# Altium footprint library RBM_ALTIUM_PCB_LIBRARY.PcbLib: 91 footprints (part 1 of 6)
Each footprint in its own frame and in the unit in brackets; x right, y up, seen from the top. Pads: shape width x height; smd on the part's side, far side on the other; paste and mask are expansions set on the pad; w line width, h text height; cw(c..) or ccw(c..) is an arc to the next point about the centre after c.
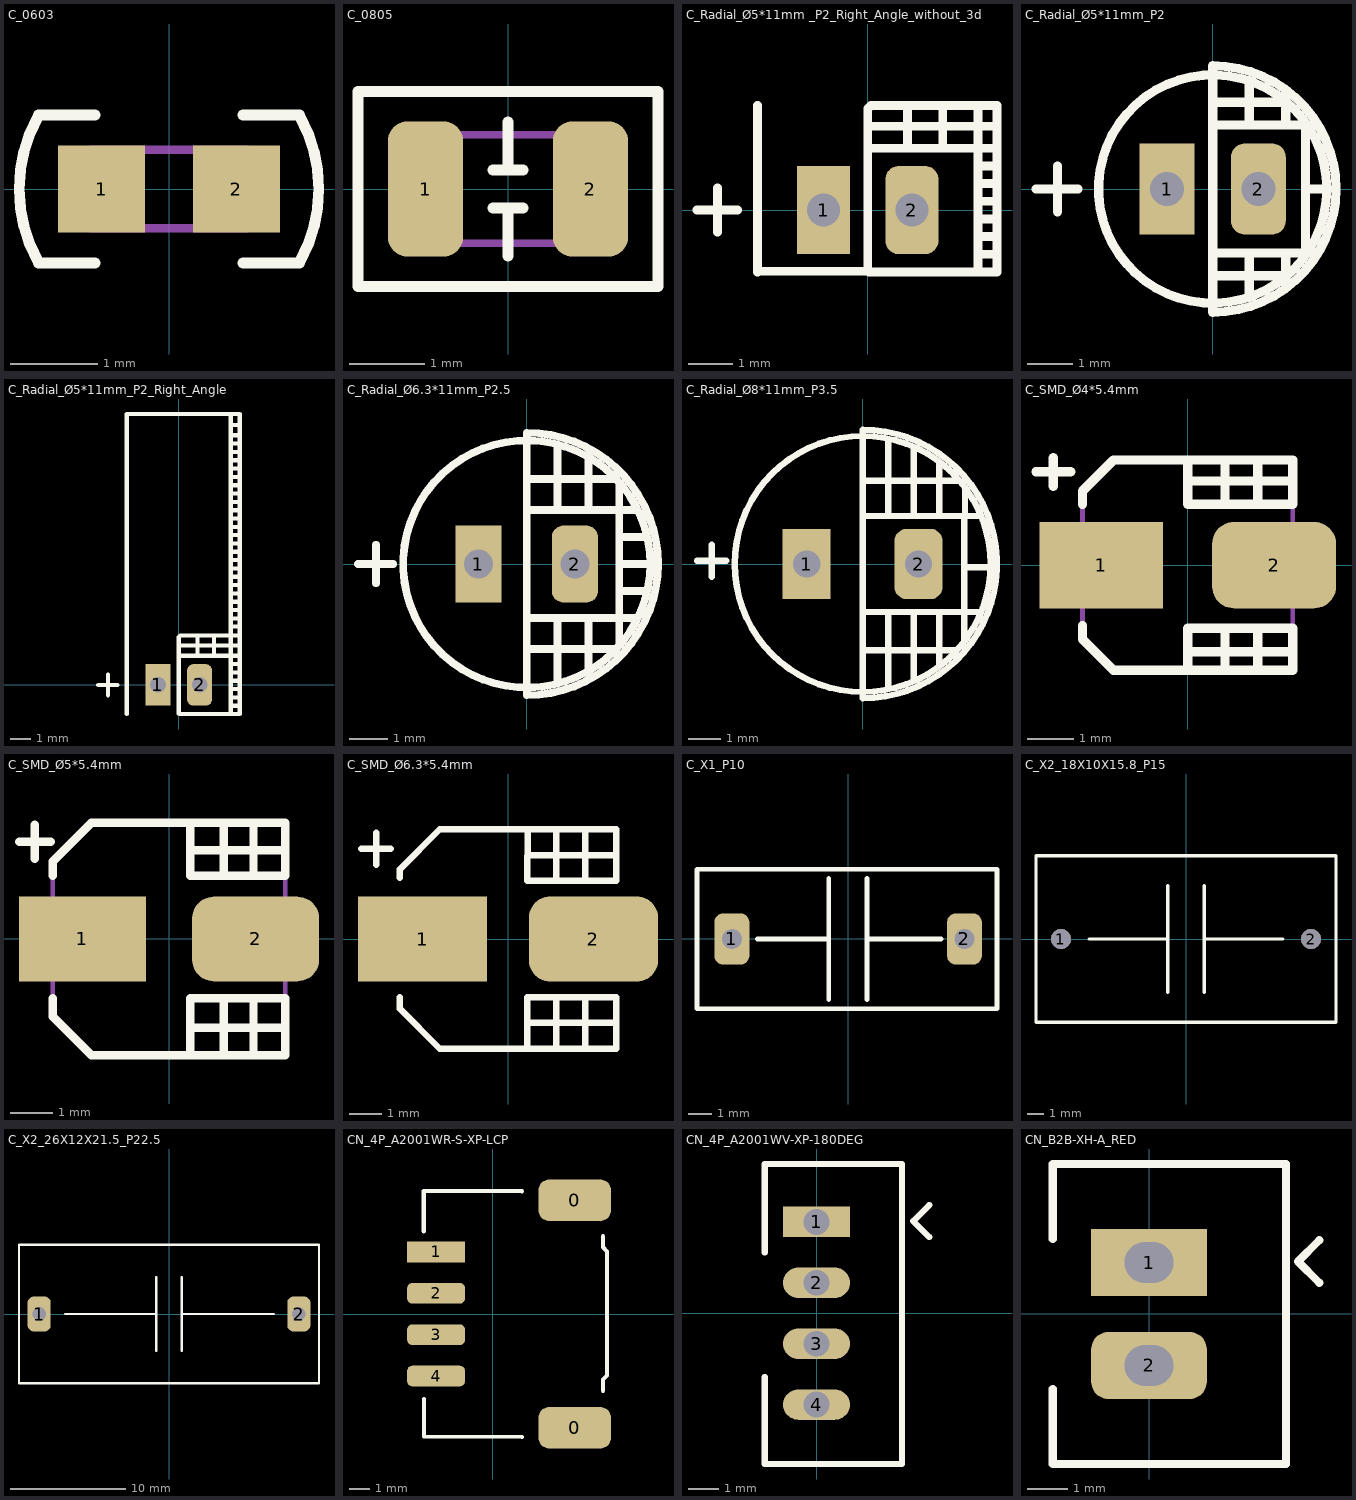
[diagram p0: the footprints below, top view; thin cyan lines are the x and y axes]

## C_0603 [mm] "0603 Multilayer Ceramic Capacitors MLCC - SMD/SMT RoHS"
height 0.87
pads (2):
  rect 1x1 smd: 1(-0.775,0) 2(0.775,0)
Top Overlay:
  lines w0.125: -1.508,-0.836 cw(c0.001,0) -1.508,0.836 ; -1.5,-0.85 -0.85,-0.85 ; -1.5,0.85 -0.85,0.85 ; 0.85,-0.85 1.5,-0.85 ; 0.85,0.85 1.5,0.85 ; 1.508,-0.836 ccw(c-0.001,0) 1.508,0.836
Assembly Top:
  lines w0.1: -0.9,-0.45 0.9,-0.45 0.9,0.45 -0.9,0.45 -0.9,-0.45
3D body "Chip2PinSM127P600-8N.step": height 0.87, standoff 0, extent -0.85,-0.45 0.85,0.45

## C_0805 [mm]
height 1
pads (2):
  rrect50% 1x1.8 smd: 1(-1.1,0) 2(1.1,0)
Top Overlay:
  lines w0.15: -0.2,-0.254 0.2,-0.254 ; -0.2,0.254 0.2,0.254 ; 0,-0.889 0,-0.254 ; 0,0.254 0,0.889 ; -2,-1.3 -2,1.3 2,1.3 2,-1.3 -2,-1.3
Mechanical 13:
  lines w0.1: -1.1,-0.725 -1.1,0.725 1.1,0.725 1.1,-0.725 -1.1,-0.725
3D body "C_0805.step": height 1, standoff 0, extent -1.1,-0.725 1.1,0.725

## C_Radial_Ø5*11mm _P2_Right_Angle_without_3d [mm]
pads (2):
  rect 1.2x2 hole 0.75: 1(-1,0)
  rrect50% 1.2x2 hole 0.75: 2(1,0)
Top Overlay:
  lines w0.2: -3.87,0.002 -2.954,0.002 ; -3.403,-0.498 -3.403,0.502 ; -2.5,2.369 -2.5,-1.4 cw(c-2.487,-1.4) -2.487,-1.387 0.013,-1.387 ; 0.1,1.4 2.929,1.4 ; 0.1,1.9 2.9,1.9 ; 0.9,1.4 0.9,2.369 ; 1.7,1.5 1.7,2.3 ; 2.5,2.369 2.5,-1.4 0.025,-1.4 0,-1.375 0,2.3 ; 2.518,-0.2 2.896,-0.2 ; 2.518,0.2 2.882,0.2 ; 2.518,0.6 2.896,0.6 ; 2.518,1 2.882,1 ; 2.551,-1.4 2.929,-1.4 2.929,2.369 0.069,2.369 0.001,2.3 ; 2.551,-1 2.929,-1 ; 2.551,-0.6 2.914,-0.6 ; 0,2.3 0.001,2.3

## C_Radial_Ø5*11mm_P2 [mm]
pads (2):
  rect 1.2x2 hole 0.75: 1(-1,0)
  rrect50% 1.2x2 hole 0.75: 2(1,0)
Top Overlay:
  lines w0.2: -3.87,0.002 -2.954,0.002 ; -3.403,-0.498 -3.403,0.502 ; 0,-1.4 2.029,-1.4 2.029,1.4 0,1.4 ; 0.1,-1.9 1.6,-1.9 ; 0.1,1.9 1.6,1.9 ; 0.8,-2.369 0.8,-1.4 ; 0.8,1.4 0.8,2.369 ; 1.6,-1.921 1.6,-1.4 ; 1.6,1.5 1.6,1.921 ; 2.092,0 2.5,0 ; 2.5,0 ccw(c0,0) 2.5,0 ; 0,-2.7 ccw(c0,0) 0,2.7 0,-2.7
3D body "User Library-Cap electro 5x11x2mm.step": height 11.53, standoff -3.27, extent -2.525,-2.525 2.526,2.525

## C_Radial_Ø5*11mm_P2_Right_Angle [mm]
pads (2):
  rect 1.2x2 hole 0.75: 1(-1,0)
  rrect50% 1.2x2 hole 0.75: 2(1,0)
Top Overlay:
  lines w0.2: -3.87,0.002 -2.954,0.002 ; -3.403,-0.498 -3.403,0.502 ; -2.5,-1.4 -2.5,13.026 2.5,13.026 ; 0.1,1.4 2.929,1.4 ; 0.1,1.9 2.9,1.9 ; 0.9,1.4 0.9,2.369 ; 1.7,1.5 1.7,2.3 ; 2.518,-0.2 2.896,-0.2 ; 2.518,0.2 2.882,0.2 ; 2.518,0.6 2.896,0.6 ; 2.518,1 2.882,1 ; 2.518,3.6 2.896,3.6 ; 2.518,4 2.882,4 ; 2.518,4.4 2.896,4.4 ; 2.518,4.8 2.882,4.8 ; 2.518,6 2.896,6 ; 2.518,6.4 2.882,6.4 ; 2.518,6.8 2.896,6.8 ; 2.518,7.2 2.882,7.2 ; 2.518,8.4 2.896,8.4 ; 2.518,8.8 2.882,8.8 ; 2.518,9.2 2.896,9.2 ; 2.518,9.6 2.882,9.6 ; 2.518,10.8 2.896,10.8 ; 2.518,11.2 2.882,11.2 ; 2.518,11.6 2.896,11.6 ; 2.518,12 2.882,12 ; 2.518,12.5 2.882,12.5 ; 2.551,-1.4 2.929,-1.4 2.929,13.026 2.5,13.026 ; 2.551,-1 2.929,-1 ; 2.551,-0.6 2.914,-0.6 ; 2.551,2.8 2.929,2.8 ; 2.551,3.2 2.914,3.2 ; 2.551,5.2 2.929,5.2 ; 2.551,5.6 2.914,5.6 ; 2.551,7.6 2.929,7.6 ; 2.551,8 2.914,8 ; 2.551,10 2.929,10 ; 2.551,10.4 2.914,10.4 ; 2.929,2.369 0.069,2.369 0.001,2.3 ; 0,2.3 0.001,2.3 ; 0,2.3 0,-1.375 0.025,-1.4 2.5,-1.4 2.5,13.026
3D body "User Library-Cap electro 5x11x2mm RA.step": height 5.53, standoff -3, extent -2.5,-0.295 2.551,13.026

## C_Radial_Ø6.3*11mm_P2.5 [mm]
pads (2):
  rect 1.2x2 hole 0.75: 1(-1.25,0)
  rrect50% 1.2x2 hole 0.75: 2(1.25,0)
Top Overlay:
  lines w0.2: -4.37,0.002 -3.454,0.002 ; -3.903,-0.498 -3.903,0.502 ; 0,-1.4 2.8,-1.4 ; 0,1.4 2.8,1.4 ; 0.1,-2.2 2.3,-2.2 ; 0.1,2.2 2.3,2.2 ; 0.8,-3.1 0.8,-1.4 ; 0.8,1.4 0.8,3.1 ; 1.6,-2.7 1.6,-1.4 ; 1.6,1.5 1.6,2.7 ; 2.4,-2.1 2.4,2.1 ; 2.4,-0.7 3.1,-0.7 ; 2.4,0 3.2,0 ; 2.4,0.7 3.1,0.7 ; 3.2,0 ccw(c0,0) 3.2,0 ; 0,-3.401 ccw(c0,0) 0,3.402 0,-3.401
3D body "User Library-Cap electro 6_3x11x2_5mm.step": height 11.53, standoff -3.01, extent -3.175,-3.175 3.176,3.176

## C_Radial_Ø8*11mm_P3.5 [mm]
pads (2):
  rect 1.5x2.2 hole 0.85: 1(-1.75,0)
  rrect50% 1.5x2.2 hole 0.85: 2(1.75,0)
Top Overlay:
  circle w0.2: c0,0 r4
  lines w0.1: 0,0 0,4
  lines w0.2: -5.178,0.1 -4.262,0.1 ; -4.711,-0.4 -4.711,0.6 ; 0,-2.7 2.9,-2.7 ; 0,-1.5 3.7,-1.5 ; 0,1.5 3.7,1.5 ; 0,2.6 3,2.6 ; 0.8,-3.9 0.8,-1.5 ; 0.8,1.5 0.8,3.9 ; 1.6,-3.6 1.6,-1.5 ; 1.6,1.5 1.6,3.6 ; 2.4,-3.2 2.4,-1.6 ; 2.4,1.5 2.4,3.2 ; 3.176,-2.4 3.176,-1.524 3.176,1.476 3.2,1.5 3.2,2.4 ; 3.2,-0.1 3.9,-0.1 ; 0,-4.2 ccw(c0,0) 0,4.2 0,-4.2
3D body "User Library-Cap electro 8x11_5x3_5mm.step": height 12.03, standoff -3.48, extent -4.025,-4.025 4.026,4.026

## C_SMD_Ø4*5.4mm [mm]
height 5.8
pads (2):
  rect 2.65x1.85 smd: 1(-1.85,0)
  rrect50% 2.65x1.85 smd: 2(1.85,0)
Top Overlay:
  lines w0.2: -3.245,2 -2.5,2 ; -2.878,1.687 -2.878,2.3 ; -2.25,-1.3 -2.25,-1.587 -1.587,-2.25 2.25,-2.25 2.25,-1.35 0,-1.35 0,-2.163 ; -2.25,1.3 -2.25,1.587 -1.587,2.25 2.25,2.25 2.25,1.3 0,1.3 ; 0,-1.85 2.25,-1.85 ; 0,1.8 2.25,1.8 ; 0,1.9 0,1.3 ; 0,2.25 0,1.3 ; 0.8,-2.175 0.8,-1.35 ; 0.8,1.3 0.8,2.25 ; 1.5,-2.175 1.5,-1.35 ; 1.5,1.3 1.5,2.25
Mechanical 13:
  lines w0.1: -2.25,-1.587 -2.25,1.587 -1.587,2.25 2.25,2.25 2.25,-2.25 -1.587,-2.25 -2.25,-1.587
3D body "CAPAE4643X58M.step": height 5.8, standoff 0, extent -2.275,-2.25 2.275,2.25

## C_SMD_Ø5*5.4mm [mm]
height 5.8
pads (2):
  rect 3x2 smd: 1(-2.05,0)
  rrect50% 3x2 smd: 2(2.05,0)
Top Overlay:
  lines w0.2: -3.545,2.3 -2.8,2.3 ; -3.178,1.9 -3.178,2.7 ; -2.75,-1.4 -2.75,-1.837 -1.838,-2.75 2.75,-2.75 2.75,-1.4 0.5,-1.4 ; -2.75,1.5 -2.75,1.837 -1.838,2.75 2.75,2.75 2.75,1.5 0.5,1.5 ; 0.5,-2.75 0.5,-1.4 ; 1.3,-1.4 1.3,-2.75 2,-2.75 2,-1.4 ; 1.3,1.5 1.3,2.75 0.5,2.75 0.5,1.5 ; 2,1.5 2,2.75 ; 2.75,-2.1 0.5,-2.1 0.5,-1.4 ; 2.75,2.1 0.5,2.1 0.5,1.5
Mechanical 13:
  lines w0.1: -2.75,-1.837 -1.838,-2.75 2.75,-2.75 2.75,2.75 -1.838,2.75 -2.75,1.837 -2.75,-1.837
3D body "CAPAE5653X58M.step": height 5.8, standoff 0, extent -2.775,-2.75 2.775,2.75

## C_SMD_Ø6.3*5.4mm [mm] "SMD 6.3x5.4mm Aluminum Electrolytic Capacitors - SMD RoHS"
height 6
pads (2):
  rect 4x2.65 smd: 1(-2.65,0)
  rrect50% 4x2.65 smd: 2(2.65,0)
Top Overlay:
  lines w0.2: -4.545,2.8 -3.629,2.8 ; -4.078,2.3 -4.078,3.3 ; -3.35,-1.8 -3.35,-2.163 -2.112,-3.4 3.35,-3.4 3.35,-1.8 0.6,-1.8 0.6,-3.4 ; -3.35,1.9 -3.35,2.163 -2.112,3.4 3.35,3.4 3.35,1.8 0.602,1.8 0.619,3.4 ; 0.6,-2.6 3.35,-2.6 ; 0.61,2.6 3.35,2.6 ; 1.5,-3.3 1.5,-1.8 ; 1.5,1.9 1.5,3.4 ; 2.4,-3.4 2.4,-1.8 ; 2.4,1.9 2.4,3.4
3D body: height 1.94, standoff 0, extent -3.4,-3.4 3.4,3.4
3D body: height 5.8, standoff 0, extent -3.4,-3.4 3.4,3.4

## C_X1_P10 [mm]
pads (2):
  rrect50% 1.5x2.2 hole 0.85: 1(-5,0) 2(5,0)
Top Overlay:
  lines w0.2: -3.9,-0.001 -0.84,0 ; -0.84,-2.6 -0.84,2.6 ; 0.807,-2.6 0.807,2.6 ; 0.807,0 4,0 ; -6.5,-3 -6.5,3 6.4,3 6.4,-3 -6.5,-3
3D body: height 11.89, standoff 0.68, extent -6.414,-2.921 6.35,2.921
3D body: height 1.5, standoff -2, extent -5.297,-0.254 -4.699,0.345
3D body: height 1.5, standoff -2, extent 4.699,-0.254 5.297,0.345

## C_X2_18X10X15.8_P15 [mm]
pads (2):
  round 1.2 / inner rrect50% 2x3 / far side rrect50% 2x3 hole 1.2: 1(-7.5,0) 2(7.5,0)
Top Overlay:
  lines w0.2: -5.8,0 -1.1,0 ; -1.1,-3.2 -1.1,3.2 ; 1.1,-3.2 1.1,3.2 ; 1.1,0 5.8,0 ; -9,-5 -9,5 9,5 9,-5 -9,-5
3D body: height 3, standoff -2, extent 7.103,-0.399 7.9,0.399
3D body: height 3, standoff -2, extent -7.898,-0.399 -7.102,0.399
3D body: height 15.8, standoff 0.2, extent -9,-5 9,5

## C_X2_26X12X21.5_P22.5 [mm]
pads (2):
  rrect50% 2x3 hole 1.2: 1(-11.25,0) 2(11.25,0)
Top Overlay:
  lines w0.2: -9,0 -1.1,0 ; -1.1,-3.2 -1.1,3.2 ; 1.1,-3.2 1.1,3.2 ; 1.1,0 9.1,0 ; -13,-6 13,-6 13,6 -13,6 -13,-6
3D body: height 21.5, standoff 0.2, extent -13,-6 13,6
3D body: height 3, standoff -2, extent -11.648,-0.399 -10.852,0.399
3D body: height 3, standoff -2, extent 10.852,-0.399 11.648,0.399

## CN_4P_A2001WR-S-XP-LCP [mm]
pads (7):
  rrect50% 3.5x2 smd: 0(3.95,-5.5) 0(3.95,5.5)
  rect 2.8x1 smd: 1(-2.75,3)
  rrect50% 2.8x1 smd: 2(-2.75,1) 3(-2.75,-1) 4(-2.75,-3)
  round 0.5 on Top Overlay: ""(-4,4.6)
Top Overlay:
  lines w0.2: -3.35,4 -3.35,5.95 1.4,5.93 ; -3.334,-4.1 -3.334,-5.925 1.4,-5.945 ; 5.319,-3.712 5.319,-3.17 5.515,-2.974 5.515,3.029 5.319,3.225 5.319,3.76
3D body "S4B-PH-SM4-TB.STEP": height 5.6, standoff 0, extent -3.35,-5.95 5.25,5.95

## CN_4P_A2001WV-XP-180DEG [mm] "Top Entry Header 1.25mm pitch 1X4pin  180° long"
pads (4):
  rect 2.2x1 hole 0.85: 1(0,3)
  oval 2.2x1 hole 0.85: 2(0,1) 3(0,-1) 4(0,-3)
Top Overlay:
  lines w0.2: -1.7,-2.1 -1.7,-4.95 2.8,-4.95 2.8,4.9 -1.7,4.9 -1.7,2 ; 3.7,2.5 3.175,3.025 3.7,3.55
3D body "B4B-PH-K-S.STEP": height 6, standoff -3.4, extent -1.7,-4.95 2.8,4.95

## CN_B2B-XH-A_RED [mm]
pads (2):
  rect 2.85x1.65 hole 1.2 slot 1 at 90 deg: 1(0,1.27)
  rrect50% 2.85x1.65 hole 1.2 slot 1 at 90 deg: 2(0,-1.27)
Top Overlay:
  lines w0.2: -2.375,-1.85 -2.375,-3.7 3.375,-3.7 3.375,3.7 -2.375,3.7 -2.375,1.85 ; 4.2,0.77 3.675,1.295 4.2,1.82
3D body: height 7, standoff -3.5, extent -0.35,0.925 0.35,1.615
3D body: height 7, standoff -3.5, extent -0.35,-1.615 0.35,-0.925
3D body "B2B-XH-A.STEP": height 7, standoff -3.4, extent -2.375,-3.7 3.375,3.7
